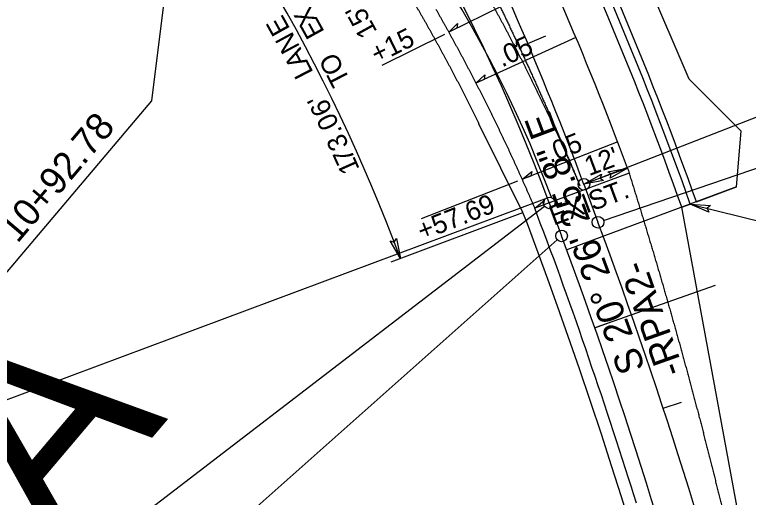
# Model space of a CAD drawing. Extents: x 1761082 to 1764358, y 421907 to 425434.
# Drawn here: x 1762765.1 to 1762953.8, y 423293.6 to 423417.6 of the extents above; entities that cross this region are included whole.
import ezdxf

# ---------------------------------------------------------------- set-up
doc = ezdxf.new("R2010")
doc.units = 0
for name, color, linetype in [('MARK HOOKS CENTER LEFT TURN ARROW CELL', 7, 'Continuous'), ('MARK HOOKS CENTER STRAIGHT LEFT TURN ARROW CELL', 7, 'Continuous'), ('MARK HOOKS STRAIGHT RIGHT TURN ARROW CELL', 7, 'Continuous'), ('MARK STRAIGHT RIGHT ARROW CELL', 7, 'Continuous'), ('MARK UTURN ARROW CELL', 7, 'Continuous'), ('Prop Conc Shoulder Berm Gutter', 7, 'Continuous'), ('Prop Geotechnical Rock Plating', 7, 'Continuous'), ('Prop Mkg 3ft Min Skp 3ft Wide White', 7, 'Continuous'), ('Prop Mkg 3ft Min Skp 9ft Wide White', 7, 'Continuous'), ('Prop Mkg Min Skp 6ft Yellow', 7, 'Continuous'), ('Prop Mkg Skp Wht', 7, 'Continuous'), ('Prop Mkg Solid White Multiple Diagonals V8i', 7, 'Continuous'), ('Prop Mkg Solid White Stop Bar', 7, 'Continuous'), ('Prop Mkg Solid Yel Skip LT', 7, 'Continuous'), ('Prop Mkg Solid Yel Skip RT', 7, 'Continuous'), ('Prop Mkg Solid Yellow Lane Line', 7, 'Continuous'), ('Prop Mkr CR 80ft Spc', 7, 'Continuous'), ('Prop Mkr Yel 80ft Spc', 7, 'Continuous'), ('Scratch_Level_0', 7, 'Continuous'), ('Scratch_Level_1', 7, 'Continuous'), ('Scratch_Level_5', 7, 'Continuous')]:
    doc.layers.add(name, color=color, linetype=linetype)

msp = doc.modelspace()

# ---------------------------------------------------------------- linework, layer by layer
at = {"layer": 'MARK HOOKS CENTER STRAIGHT LEFT TURN ARROW CELL'}
for p, q in [((1762897.11, 423410.19), (1762901.71, 423412.14)), ((1762914.33, 423337.15), (1762919.05, 423338.81)), ((1762931.92, 423316.47), (1762936.67, 423318.03))]:
    msp.add_line(p, q, dxfattribs=at)
at = {"layer": 'MARK STRAIGHT RIGHT ARROW CELL'}
msp.add_line((1762911.52, 423374.01), (1762915.16, 423364.26), dxfattribs=at)
for centre, radius, start, end in [((1762097.24, 423070.52), 869, 20.4405, 32.46275), ((1761687.64, 422906.76), 1310, 14.12093, 20.4405)]:
    msp.add_arc(centre, radius, start, end, dxfattribs=at)
at = {"layer": 'MARK UTURN ARROW CELL'}
for points in [[(1762912.92, 423374.55), (1763065.93, 423434.24), (1763148.72, 423531.97)], [(1762916.58, 423364.74), (1763079.19, 423420.23), (1763161.99, 423517.97)], [(1762815.42, 423516.34), (1762800.3, 423395.47), (1762717.5, 423297.73)], [(1762901.44, 423368.33), (1762759.45, 423259.49), (1762680.33, 423166.09)], [(1762904.67, 423359.77), (1762774.23, 423243.86), (1762695.38, 423150.78)]]:
    msp.add_lwpolyline(points, dxfattribs=at)
for centre in [(1762911.52, 423374.01), (1762902.63, 423369.25), (1762915.16, 423364.26), (1762905.79, 423360.77)]:
    msp.add_circle(centre, 1.5, dxfattribs=at)
at = {"layer": 'Prop Conc Shoulder Berm Gutter'}
msp.add_line((1762936.7, 423368.16), (1762938.9, 423368.94), dxfattribs=at)
msp.add_arc((1762097.24, 423070.52), 893, 19.5225, 32.46275, dxfattribs=at)
at = {"layer": 'Prop Geotechnical Rock Plating'}
for p, q in [((1762951.99, 423387.64), (1762938.59, 423401.07)), ((1762950.79, 423373.33), (1762951.99, 423387.64)), ((1762940.47, 423369.52), (1762950.79, 423373.33))]:
    msp.add_line(p, q, dxfattribs=at)
msp.add_lwpolyline([(1762938.59, 423401.07), (1762917.13, 423451.29), (1762907.85, 423471.24)], dxfattribs=at)
msp.add_arc((1762097.24, 423070.52), 894.67, 19.5239, 32.46275, dxfattribs=at)
at = {"layer": 'Prop Mkg 3ft Min Skp 3ft Wide White'}
for p, q in [((1762911.52, 423374.01), (1762915.16, 423364.26)), ((1762902.63, 423369.25), (1762905.79, 423360.77))]:
    msp.add_line(p, q, dxfattribs=at)
for centre, radius, start, end in [((1762097.24, 423070.52), 869, 20.4405, 32.46275), ((1762434.11, 423194.63), 500, 20.4405, 40.2713), ((1761687.64, 422906.76), 1310, 14.12093, 20.4405), ((1761687.64, 422906.76), 1300, 14.12093, 20.4405)]:
    msp.add_arc(centre, radius, start, end, dxfattribs=at)
at = {"layer": 'Prop Mkg 3ft Min Skp 9ft Wide White'}
msp.add_arc((1762097.24, 423070.52), 893, 19.5225, 32.46275, dxfattribs=at)
at = {"layer": 'Prop Mkg Skp Wht'}
msp.add_lwpolyline([(1762925.04, 423292.06), (1762924.29, 423294.44), (1762923.77, 423296.14), (1762923, 423298.52), (1762922.23, 423300.9), (1762921.47, 423303.28), (1762920.7, 423305.66), (1762919.93, 423308.04), (1762919.16, 423310.42), (1762918.4, 423312.79), (1762917.64, 423315.13), (1762916.84, 423317.5), (1762916.03, 423319.86), (1762915.22, 423322.23), (1762914.41, 423324.59), (1762913.61, 423326.96), (1762912.8, 423329.33), (1762911.99, 423331.69), (1762911.18, 423334.06), (1762910.38, 423336.42), (1762909.61, 423338.68), (1762908.76, 423341.03), (1762907.92, 423343.38), (1762907.08, 423345.74), (1762906.23, 423348.09), (1762905.39, 423350.44), (1762904.55, 423352.8), (1762903.86, 423354.71), (1762902.98, 423357.04), (1762902.09, 423359.38), (1762901.21, 423361.72), (1762900.32, 423364.06), (1762899.44, 423366.4), (1762898.89, 423367.85)], dxfattribs=at)
msp.add_arc((1762097.24, 423070.52), 881, 20.4405, 32.46275, dxfattribs=at)
for points in [[(1762873.48, 423418.99), (1762873.86, 423418.32), (1762874.24, 423417.65), (1762874.62, 423416.98), (1762875, 423416.31), (1762875.38, 423415.64), (1762875.75, 423414.96), (1762876.13, 423414.29), (1762876.5, 423413.62), (1762876.88, 423412.94), (1762877.25, 423412.27), (1762877.62, 423411.59), (1762877.99, 423410.92), (1762878.36, 423410.24), (1762878.73, 423409.56), (1762879.09, 423408.89), (1762879.46, 423408.21), (1762879.82, 423407.53), (1762880.19, 423406.85), (1762880.55, 423406.17), (1762880.91, 423405.49), (1762881.27, 423404.81), (1762881.63, 423404.12), (1762881.99, 423403.44), (1762882.35, 423402.76), (1762882.71, 423402.07), (1762883.06, 423401.39), (1762883.42, 423400.7), (1762883.77, 423400.02), (1762884.12, 423399.33), (1762884.47, 423398.65), (1762884.82, 423397.96), (1762885.17, 423397.27), (1762885.52, 423396.58), (1762885.87, 423395.89), (1762886.22, 423395.2), (1762886.56, 423394.51), (1762886.91, 423393.82), (1762887.25, 423393.13), (1762887.59, 423392.44), (1762887.93, 423391.74), (1762888.27, 423391.05), (1762888.61, 423390.36), (1762888.95, 423389.66), (1762889.28, 423388.97), (1762889.62, 423388.27), (1762889.95, 423387.57), (1762890.29, 423386.88), (1762890.62, 423386.18), (1762890.95, 423385.48), (1762891.28, 423384.78), (1762891.61, 423384.08), (1762891.94, 423383.38), (1762892.27, 423382.68), (1762892.59, 423381.98), (1762892.92, 423381.28), (1762893.24, 423380.58), (1762893.56, 423379.88), (1762893.89, 423379.17), (1762894.21, 423378.47), (1762894.53, 423377.77), (1762894.84, 423377.06), (1762895.16, 423376.36), (1762895.48, 423375.65), (1762895.79, 423374.94), (1762896.11, 423374.24), (1762896.42, 423373.53), (1762896.73, 423372.82), (1762897.04, 423372.11), (1762897.35, 423371.4), (1762897.66, 423370.69), (1762897.97, 423369.98), (1762898.28, 423369.27), (1762898.89, 423367.85)], [(1762922.77, 423378.2), (1762922.97, 423377.55), (1762923.17, 423376.9), (1762923.37, 423376.26), (1762923.56, 423375.61), (1762923.76, 423374.96), (1762923.96, 423374.31), (1762924.16, 423373.67), (1762924.36, 423373.02), (1762924.56, 423372.37), (1762924.76, 423371.73), (1762924.95, 423371.08), (1762925.15, 423370.43), (1762925.35, 423369.78), (1762925.55, 423369.14), (1762925.75, 423368.49), (1762925.95, 423367.84), (1762926.15, 423367.19), (1762926.35, 423366.53), (1762926.55, 423365.88), (1762926.75, 423365.23), (1762926.95, 423364.58), (1762927.14, 423363.92), (1762927.34, 423363.27), (1762927.54, 423362.62), (1762927.74, 423361.96), (1762927.93, 423361.31), (1762928.13, 423360.66), (1762928.33, 423360), (1762928.52, 423359.35), (1762928.72, 423358.7), (1762928.92, 423358.04), (1762929.11, 423357.39), (1762929.31, 423356.73), (1762929.5, 423356.08), (1762929.69, 423355.43), (1762929.89, 423354.77), (1762930.08, 423354.12), (1762930.27, 423353.46), (1762930.47, 423352.81), (1762930.66, 423352.15), (1762930.85, 423351.5), (1762931.04, 423350.84), (1762931.23, 423350.19), (1762931.42, 423349.53), (1762931.62, 423348.88), (1762931.81, 423348.22), (1762932, 423347.57), (1762932.19, 423346.91), (1762932.37, 423346.26), (1762932.56, 423345.6), (1762932.75, 423344.95), (1762932.94, 423344.29), (1762933.13, 423343.64), (1762933.32, 423342.98), (1762933.5, 423342.33), (1762933.69, 423341.67), (1762933.88, 423341.01), (1762934.06, 423340.36), (1762934.25, 423339.7), (1762934.43, 423339.05), (1762934.62, 423338.39), (1762934.8, 423337.73), (1762934.99, 423337.08), (1762935.17, 423336.42), (1762935.36, 423335.76), (1762935.54, 423335.11), (1762935.72, 423334.45), (1762935.9, 423333.79), (1762936.09, 423333.14), (1762936.27, 423332.48), (1762936.45, 423331.82), (1762936.63, 423331.17), (1762936.81, 423330.51), (1762936.99, 423329.85)], [(1762936.99, 423329.85), (1762937.17, 423329.2), (1762937.35, 423328.54), (1762937.53, 423327.88), (1762937.71, 423327.22), (1762937.89, 423326.57), (1762938.07, 423325.91), (1762938.25, 423325.25), (1762938.43, 423324.59), (1762938.6, 423323.93), (1762938.78, 423323.28), (1762938.96, 423322.62), (1762939.13, 423321.96), (1762939.31, 423321.3), (1762939.49, 423320.64), (1762939.66, 423319.99), (1762939.84, 423319.33), (1762940.01, 423318.67), (1762940.18, 423318.01), (1762940.36, 423317.35), (1762940.53, 423316.69), (1762940.71, 423316.04), (1762940.88, 423315.38), (1762941.05, 423314.72), (1762941.22, 423314.06), (1762941.4, 423313.4), (1762941.57, 423312.74), (1762941.74, 423312.08), (1762941.91, 423311.42), (1762942.08, 423310.76), (1762942.25, 423310.1), (1762942.42, 423309.44), (1762942.59, 423308.79), (1762942.76, 423308.13), (1762942.93, 423307.47), (1762943.1, 423306.81), (1762943.26, 423306.15), (1762943.43, 423305.49), (1762943.6, 423304.83), (1762943.77, 423304.17), (1762943.93, 423303.51), (1762944.1, 423302.85), (1762944.27, 423302.19), (1762944.43, 423301.53), (1762944.6, 423300.87), (1762944.76, 423300.21), (1762944.93, 423299.55), (1762945.09, 423298.89), (1762945.26, 423298.23), (1762945.42, 423297.57), (1762945.58, 423296.9), (1762945.75, 423296.24), (1762945.91, 423295.58), (1762946.07, 423294.92), (1762946.23, 423294.26), (1762946.39, 423293.6), (1762946.55, 423292.94), (1762946.72, 423292.28), (1762946.88, 423291.62), (1762947.04, 423290.96), (1762947.2, 423290.29), (1762947.36, 423289.63), (1762947.51, 423288.97), (1762947.67, 423288.31), (1762947.83, 423287.65), (1762947.99, 423286.99), (1762948.15, 423286.33), (1762948.31, 423285.66), (1762948.46, 423285), (1762948.62, 423284.34), (1762948.78, 423283.68), (1762948.93, 423283.02), (1762949.09, 423282.36), (1762949.4, 423281.03)]]:
    msp.add_spline(points, degree=3, dxfattribs=at)
at = {"layer": 'Prop Mkg Solid White Multiple Diagonals V8i'}
for p, q in [((1762950.79, 423373.33), (1762907.11, 423357.2)), ((1762902.63, 423369.25), (1762905.79, 423360.77))]:
    msp.add_line(p, q, dxfattribs=at)
for centre, radius, start, end in [((1762434.11, 423194.63), 500, 20.4405, 40.2713), ((1761687.64, 422906.76), 1300, 14.12093, 20.4405)]:
    msp.add_arc(centre, radius, start, end, dxfattribs=at)
at = {"layer": 'Prop Mkg Solid White Stop Bar'}
for p, q in [((1762895.87, 423366.73), (1762884.55, 423389.56)), ((1762952.62, 423281.99), (1762936.7, 423368.16))]:
    msp.add_line(p, q, dxfattribs=at)
msp.add_lwpolyline([(1762927.21, 423274.45), (1762926.2, 423277.73), (1762923.72, 423285.73), (1762921.22, 423293.7), (1762918.67, 423301.68), (1762916.03, 423309.79), (1762913.25, 423318.16), (1762910.39, 423326.59), (1762907.51, 423334.91), (1762904.76, 423342.71), (1762902.3, 423349.61), (1762899.81, 423356.38), (1762896.99, 423363.85), (1762895.87, 423366.73)], dxfattribs=at)
msp.add_arc((1762097.24, 423070.52), 890.67, 19.5225, 32.46275, dxfattribs=at)
for points in [[(1762839.29, 423464.23), (1762839.74, 423463.61), (1762840.19, 423463), (1762840.63, 423462.39), (1762841.08, 423461.77), (1762841.53, 423461.16), (1762841.97, 423460.54), (1762842.42, 423459.92), (1762842.86, 423459.31), (1762843.3, 423458.69), (1762843.74, 423458.07), (1762844.19, 423457.45), (1762844.62, 423456.83), (1762845.06, 423456.21), (1762845.5, 423455.59), (1762845.94, 423454.97), (1762846.37, 423454.34), (1762846.81, 423453.72), (1762847.24, 423453.09), (1762847.68, 423452.47), (1762848.11, 423451.84), (1762848.54, 423451.22), (1762848.97, 423450.59), (1762849.4, 423449.96), (1762849.83, 423449.33), (1762850.25, 423448.7), (1762850.68, 423448.07), (1762851.11, 423447.44), (1762851.53, 423446.81), (1762851.95, 423446.18), (1762852.38, 423445.54), (1762852.8, 423444.91), (1762853.22, 423444.27), (1762853.64, 423443.64), (1762854.06, 423443), (1762854.48, 423442.37), (1762854.89, 423441.73), (1762855.31, 423441.09), (1762855.72, 423440.45), (1762856.14, 423439.81), (1762856.55, 423439.17), (1762856.96, 423438.53), (1762857.37, 423437.89), (1762857.78, 423437.25), (1762858.19, 423436.6), (1762858.6, 423435.96), (1762859.01, 423435.32), (1762859.41, 423434.67), (1762859.82, 423434.03), (1762860.22, 423433.38), (1762860.63, 423432.73), (1762861.03, 423432.08), (1762861.43, 423431.44), (1762861.83, 423430.79), (1762862.23, 423430.14), (1762862.63, 423429.49), (1762863.02, 423428.84), (1762863.42, 423428.18), (1762863.82, 423427.53), (1762864.21, 423426.88), (1762864.6, 423426.23), (1762865, 423425.57), (1762865.39, 423424.92), (1762865.78, 423424.26), (1762866.17, 423423.6), (1762866.56, 423422.95), (1762866.94, 423422.29), (1762867.33, 423421.63), (1762867.71, 423420.97), (1762868.1, 423420.31), (1762868.48, 423419.65), (1762868.86, 423418.99), (1762869.25, 423418.33), (1762869.63, 423417.67), (1762870.01, 423417)], [(1762870, 423417.01), (1762870.38, 423416.34), (1762870.76, 423415.68), (1762871.14, 423415.01), (1762871.51, 423414.35), (1762871.89, 423413.68), (1762872.26, 423413.01), (1762872.63, 423412.35), (1762873, 423411.68), (1762873.37, 423411.01), (1762873.74, 423410.34), (1762874.11, 423409.67), (1762874.48, 423409), (1762874.84, 423408.33), (1762875.21, 423407.66), (1762875.57, 423406.98), (1762875.94, 423406.31), (1762876.3, 423405.64), (1762876.66, 423404.96), (1762877.02, 423404.29), (1762877.38, 423403.61), (1762877.74, 423402.94), (1762878.09, 423402.26), (1762878.45, 423401.58), (1762878.8, 423400.91), (1762879.16, 423400.23), (1762879.51, 423399.55), (1762879.86, 423398.87), (1762880.21, 423398.19), (1762880.56, 423397.51), (1762880.91, 423396.83), (1762881.26, 423396.14), (1762881.61, 423395.46), (1762881.95, 423394.78), (1762882.3, 423394.1), (1762882.64, 423393.41), (1762882.98, 423392.73), (1762883.32, 423392.04), (1762883.66, 423391.35), (1762884, 423390.67), (1762884.34, 423389.98), (1762884.55, 423389.56)]]:
    msp.add_spline(points, degree=3, dxfattribs=at)
at = {"layer": 'Prop Mkg Solid Yel Skip RT'}
for p, q in [((1762875.66, 423412.53), (1762859.57, 423404.59)), ((1762922.77, 423378.2), (1762911.52, 423374.01)), ((1762894.48, 423374.81), (1762869.7, 423365.11)), ((1762861.97, 423354.09), (1762895.87, 423366.73))]:
    msp.add_line(p, q, dxfattribs=at)
msp.add_lwpolyline([(1762938.9, 423368.94), (1763023.66, 423348.02), (1763064.14, 423395.8)], dxfattribs=at)
msp.add_arc((1762434.11, 423194.63), 459.13, 20.4405, 40.2713, dxfattribs=at)
at = {"layer": 'Prop Mkg Solid Yellow Lane Line'}
for points in [[(1762917.68, 423377.24), (1762922.77, 423378.2), (1762918.28, 423375.56), (1762918.57, 423376.63)], [(1762916.61, 423374.97), (1762911.52, 423374.01), (1762916.02, 423376.65), (1762915.72, 423375.57)], [(1762943.65, 423366.87), (1762938.9, 423368.94), (1762944.1, 423368.59), (1762943.25, 423367.87)], [(1762863.35, 423360.06), (1762864.33, 423354.97), (1762861.67, 423359.45), (1762862.75, 423359.16)]]:
    msp.add_lwpolyline(points, close=True, dxfattribs=at)
at = {"layer": 'Prop Mkr CR 80ft Spc'}
msp.add_line((1762621.04, 423265.75), (1762902.15, 423370.52), dxfattribs=at)
at = {"layer": 'Prop Mkr Yel 80ft Spc'}
msp.add_circle((1762903.09, 423370.87), 0.0417, dxfattribs=at)
msp.add_arc((1762621.04, 423265.75), 301, 20.4405, 49.878, dxfattribs=at)
at = {"layer": 'Scratch_Level_0'}
for p, q in [((1762894.31, 423409.37), (1762893.41, 423410.09)), ((1762894.31, 423409.37), (1762894.2, 423410.79)), ((1762945.31, 423348.02), (1762914.33, 423337.15))]:
    msp.add_line(p, q, dxfattribs=at)
for points in [[(1762873.26, 423452.65), (1762873.54, 423452.13), (1762873.81, 423451.61), (1762874.09, 423451.09), (1762874.37, 423450.57), (1762874.64, 423450.05), (1762874.92, 423449.53), (1762875.19, 423449.01), (1762875.47, 423448.49), (1762875.75, 423447.96), (1762876.02, 423447.44), (1762876.29, 423446.92), (1762876.57, 423446.4), (1762876.84, 423445.88), (1762877.12, 423445.35), (1762877.39, 423444.83), (1762877.66, 423444.31), (1762877.93, 423443.78), (1762878.2, 423443.26), (1762878.48, 423442.74), (1762878.75, 423442.21), (1762879.02, 423441.69), (1762879.29, 423441.17), (1762879.56, 423440.64), (1762879.83, 423440.12), (1762880.1, 423439.59), (1762880.37, 423439.07), (1762880.64, 423438.54), (1762880.9, 423438.02), (1762881.17, 423437.49), (1762881.44, 423436.97), (1762881.71, 423436.44), (1762881.97, 423435.91), (1762882.24, 423435.39), (1762882.51, 423434.86), (1762882.77, 423434.33), (1762883.04, 423433.81), (1762883.3, 423433.28), (1762883.57, 423432.75), (1762883.83, 423432.22), (1762884.1, 423431.7), (1762884.36, 423431.17), (1762884.62, 423430.64), (1762884.89, 423430.11), (1762885.15, 423429.58), (1762885.41, 423429.06), (1762885.67, 423428.53), (1762885.94, 423428), (1762886.2, 423427.47), (1762886.46, 423426.94), (1762886.72, 423426.41), (1762886.98, 423425.88), (1762887.24, 423425.35), (1762887.5, 423424.82), (1762887.76, 423424.29), (1762888.02, 423423.76), (1762888.27, 423423.23), (1762888.53, 423422.7), (1762888.79, 423422.17), (1762889.05, 423421.64), (1762889.3, 423421.1), (1762889.56, 423420.57), (1762889.82, 423420.04), (1762890.07, 423419.51), (1762890.33, 423418.98), (1762890.58, 423418.44), (1762890.84, 423417.91), (1762891.09, 423417.38), (1762891.35, 423416.84), (1762891.6, 423416.31), (1762891.86, 423415.78), (1762892.11, 423415.24), (1762892.36, 423414.71), (1762892.61, 423414.18), (1762892.87, 423413.64)], [(1762884.89, 423425.82), (1762885.28, 423425.14), (1762885.66, 423424.46), (1762886.04, 423423.77), (1762886.43, 423423.09), (1762886.81, 423422.4), (1762887.19, 423421.71), (1762887.56, 423421.03), (1762887.94, 423420.34), (1762888.32, 423419.65), (1762888.69, 423418.96), (1762889.07, 423418.27), (1762889.44, 423417.58), (1762889.81, 423416.89), (1762890.19, 423416.2), (1762890.56, 423415.51), (1762890.93, 423414.81), (1762891.29, 423414.12), (1762891.66, 423413.43), (1762892.03, 423412.73), (1762892.39, 423412.04), (1762892.76, 423411.34), (1762893.12, 423410.64), (1762893.48, 423409.95), (1762893.84, 423409.25), (1762894.2, 423408.55), (1762894.56, 423407.85), (1762894.92, 423407.15), (1762895.27, 423406.45), (1762895.63, 423405.75), (1762895.98, 423405.05), (1762896.34, 423404.35), (1762896.69, 423403.64), (1762897.04, 423402.94), (1762897.39, 423402.24), (1762897.74, 423401.53), (1762898.09, 423400.83), (1762898.44, 423400.12), (1762898.78, 423399.42), (1762899.13, 423398.71), (1762899.47, 423398), (1762899.81, 423397.29), (1762900.15, 423396.59), (1762900.49, 423395.88), (1762900.83, 423395.17), (1762901.17, 423394.46), (1762901.51, 423393.75), (1762901.85, 423393.04), (1762902.18, 423392.32), (1762902.52, 423391.61), (1762902.85, 423390.9), (1762903.18, 423390.19), (1762903.51, 423389.47), (1762903.84, 423388.76), (1762904.17, 423388.04), (1762904.5, 423387.33), (1762904.82, 423386.61), (1762905.15, 423385.89), (1762905.47, 423385.18), (1762905.8, 423384.46), (1762906.12, 423383.74), (1762906.44, 423383.02), (1762906.76, 423382.3), (1762907.08, 423381.58), (1762907.4, 423380.86), (1762907.71, 423380.14), (1762908.03, 423379.42), (1762908.34, 423378.7), (1762908.65, 423377.97), (1762908.97, 423377.25), (1762909.28, 423376.53), (1762909.59, 423375.8), (1762909.9, 423375.08), (1762910.51, 423373.63)], [(1762892.87, 423413.64), (1762893.12, 423413.11), (1762893.37, 423412.57), (1762893.62, 423412.04), (1762893.87, 423411.51), (1762894.12, 423410.97), (1762894.37, 423410.43), (1762894.62, 423409.9), (1762894.87, 423409.36), (1762895.12, 423408.83), (1762895.37, 423408.29), (1762895.61, 423407.76), (1762895.86, 423407.22), (1762896.11, 423406.68), (1762896.36, 423406.15), (1762896.6, 423405.61), (1762896.85, 423405.07), (1762897.09, 423404.54), (1762897.34, 423404), (1762897.59, 423403.46), (1762897.83, 423402.92), (1762898.07, 423402.39), (1762898.32, 423401.85), (1762898.56, 423401.31), (1762898.81, 423400.77), (1762899.05, 423400.23), (1762899.29, 423399.69), (1762899.53, 423399.15), (1762899.78, 423398.62), (1762900.02, 423398.08), (1762900.26, 423397.54), (1762900.5, 423397), (1762900.74, 423396.46), (1762900.98, 423395.92), (1762901.22, 423395.38), (1762901.46, 423394.84), (1762901.7, 423394.3), (1762901.94, 423393.76), (1762902.18, 423393.21), (1762902.41, 423392.67), (1762902.65, 423392.13), (1762902.89, 423391.59), (1762903.12, 423391.05), (1762903.36, 423390.51), (1762903.6, 423389.97), (1762903.83, 423389.42), (1762904.07, 423388.88), (1762904.3, 423388.34), (1762904.54, 423387.8), (1762904.77, 423387.25), (1762905.01, 423386.71), (1762905.24, 423386.17), (1762905.47, 423385.62), (1762905.71, 423385.08), (1762905.94, 423384.54), (1762906.17, 423383.99), (1762906.4, 423383.45), (1762906.63, 423382.9), (1762906.86, 423382.36), (1762907.1, 423381.82), (1762907.33, 423381.27), (1762907.56, 423380.73), (1762907.79, 423380.18), (1762908.01, 423379.64), (1762908.24, 423379.09), (1762908.47, 423378.54), (1762908.7, 423378), (1762908.93, 423377.45), (1762909.15, 423376.91), (1762909.38, 423376.36), (1762909.61, 423375.81), (1762909.83, 423375.27), (1762910.06, 423374.72), (1762910.51, 423373.63)]]:
    msp.add_spline(points, degree=3, dxfattribs=at)
at = {"layer": 'Scratch_Level_1'}
msp.add_circle((1762903.09, 423370.87), 0.0417, dxfattribs=at)
msp.add_arc((1762621.04, 423265.75), 301, 20.4405, 49.878, dxfattribs=at)
at = {"layer": 'Scratch_Level_5'}
for p, q in [((1762903.27, 423426.16), (1762876.79, 423413.09)), ((1762909.48, 423411.74), (1762883.78, 423400)), ((1762920.24, 423384.89), (1762895.73, 423375.3)), ((1762923.17, 423376.9), (1762898.89, 423367.85))]:
    msp.add_line(p, q, dxfattribs=at)
for points in [[(1762876.79, 423413.09), (1762879.04, 423415.32), (1762878.87, 423414.11)], [(1762883.78, 423400), (1762886.09, 423402.16), (1762885.88, 423400.96)], [(1762895.73, 423375.3), (1762898.15, 423377.32), (1762897.88, 423376.14)], [(1762898.89, 423367.85), (1762901.35, 423369.84), (1762901.05, 423368.66)]]:
    msp.add_lwpolyline(points, close=True, dxfattribs=at)

# ---------------------------------------------------------------- texts
at = {"layer": 'MARK HOOKS CENTER LEFT TURN ARROW CELL'}
msp.add_text('S 20%%d 26\' 25.8" E', height=7, rotation=110.4405, dxfattribs=at).set_placement((1762927.38, 423326.84))
at = {"layer": 'MARK HOOKS STRAIGHT RIGHT TURN ARROW CELL'}
msp.add_text('-RPA2-', height=7, rotation=109.5792, dxfattribs=at).set_placement((1762937.38, 423326.02))
at = {"layer": 'MARK UTURN ARROW CELL'}
msp.add_text('-RPA1- PRC Sta.  10+92.78', height=7, rotation=49.7301, dxfattribs=at).set_placement((1762715.76, 423299.52))
at = {"layer": 'Prop Mkg Min Skp 6ft Yellow'}
for s, rotation, p in [("15' INC.", 118.8442, (1762858.5, 423413.28)), ('.05', 24.5471, (1762890.47, 423404.04)), ('.05', 21.3774, (1762902.88, 423379.42)), ('EXIST.', 20.4405, (1762903.77, 423363.38))]:
    msp.add_text(s, height=5, rotation=rotation, dxfattribs=at).set_placement(p)
at = {"layer": 'Prop Mkg Solid Yel Skip LT'}
for s, height, rotation, p in [('+15', 5, 26.2659, (1762858.27, 423404.95)), ("12'", 5, 20.4405, (1762912.85, 423376.09)), ('+57.69', 5, 21.3774, (1762869.9, 423359.5)), ('A', 50, 49.7301, (1762775.88, 423279.78))]:
    msp.add_text(s, height=height, rotation=rotation, dxfattribs=at).set_placement(p)
at = {"layer": 'Prop Mkg Solid Yel Skip RT'}
for s, rotation, p in [('X', 119.3343, (1762843.23, 423416.29)), ('E', 119.0892, (1762836.09, 423413.95)), ('E', 118.9008, (1762844.94, 423413.2)), ('N', 118.4309, (1762838.6, 423409.34)), ('A', 117.8884, (1762840.64, 423405.51)), ('L', 117.5033, (1762842.06, 423402.78)), ('O', 117.574, (1762850, 423403.68)), ('T', 117.1594, (1762851.54, 423400.69)), ("'", 116.6298, (1762845.21, 423396.56)), ('6', 116.1347, (1762846.96, 423393.01)), ('0', 115.6395, (1762848.68, 423389.45)), ('.', 115.392, (1762849.52, 423387.66)), ('3', 114.8969, (1762851.19, 423384.08)), ('7', 114.4018, (1762852.83, 423380.48)), ('1', 114.0565, (1762853.95, 423377.96))]:
    msp.add_text(s, height=5, rotation=rotation, dxfattribs=at).set_placement(p)

doc.saveas('drawing.dxf')
